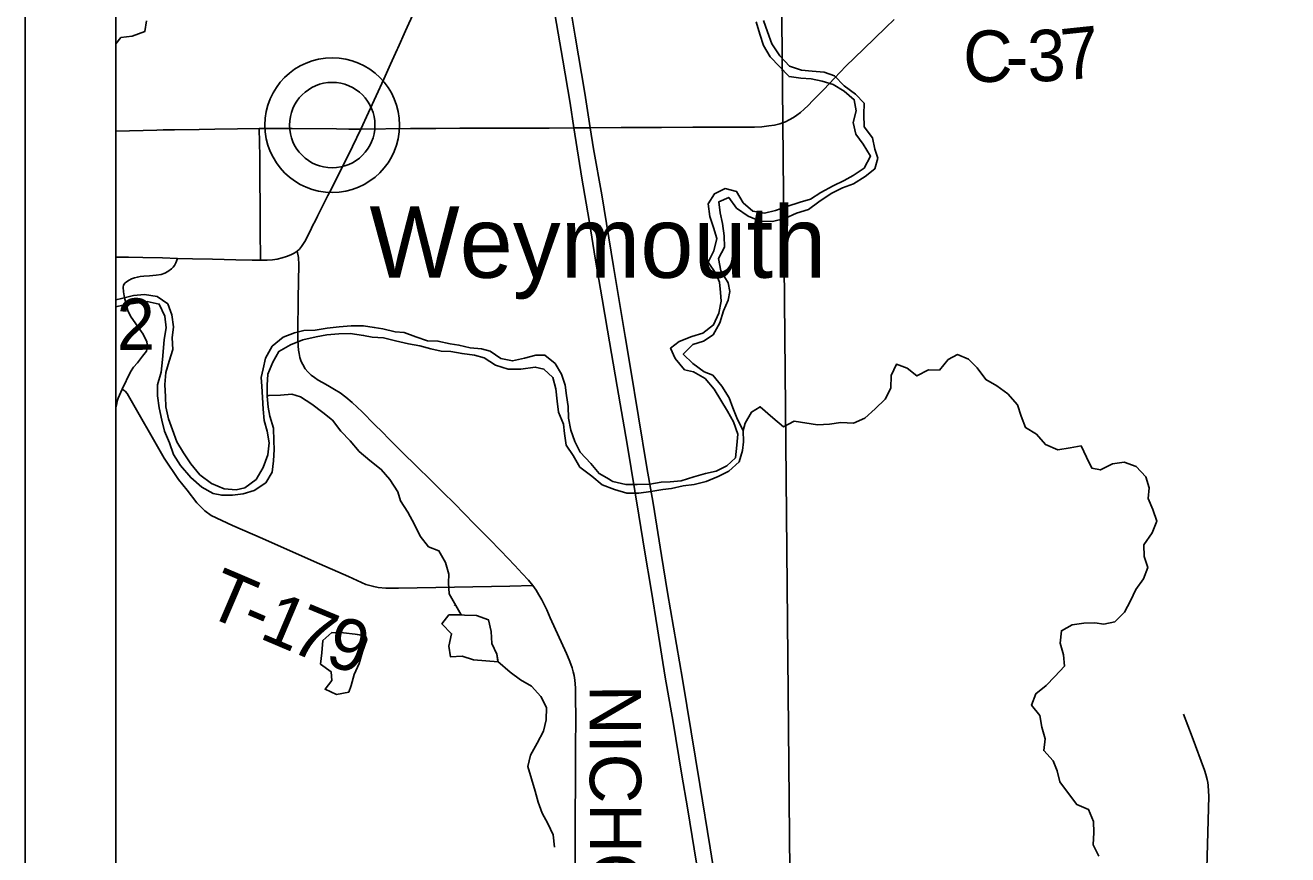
# Model space of a CAD drawing. Extents: x 0 to 34, y 0 to 22.
# Drawn here: x 2 to 3.395, y 17.117 to 18.033 of the extents above; entities that cross this region are included whole.
import ezdxf

# ---------------------------------------------------------------- set-up
doc = ezdxf.new("R2010")
doc.units = 0
for name, color, linetype in [('GM_X_Corporation', 7, 'Continuous'), ('GM_X_County_Road', 7, 'Continuous'), ('GM_X_County_Road_Text', 7, 'Continuous'), ('GM_X_Interstate_Route', 7, 'Continuous'), ('GM_X_Minor_Lake', 7, 'Continuous'), ('GM_X_Minor_River', 7, 'Continuous'), ('GM_X_Township_Road', 7, 'Continuous'), ('GM_X_Township_Road_Text', 7, 'Continuous'), ('GM_X_Unincorporated', 7, 'Continuous'), ('GM_X_Unincorporated_Location', 7, 'Continuous'), ('GM_X_Unincorporated_Text', 7, 'Continuous'), ('SH_Data', 7, 'Continuous')]:
    doc.layers.add(name, color=color, linetype=linetype)

msp = doc.modelspace()

# ---------------------------------------------------------------- linework, layer by layer
at = {"layer": 'GM_X_Corporation'}
for points in [[(2.1, 20.9), (2.1, 14.1), (7.9734, 14.1), (7.9726, 14.5453), (7.9765, 15.2637), (7.9792, 15.5481), (7.979, 15.5988), (7.9808, 15.7192), (7.9807, 15.9078), (7.9821, 16.2487), (7.9825, 16.3395), (7.9818, 16.3982), (7.9825, 16.6077), (7.9838, 16.7968), (7.9877, 17.3871), (7.9891, 17.5498), (7.991, 17.7727), (7.9901, 18.1613)], [(3.735, 14.5275), (3.3839, 14.5264), (3.3511, 14.525), (2.8655, 14.5214), (2.8502, 15.8768), (2.8488, 16.2), (2.8487, 16.2273), (2.8487, 16.232), (2.8477, 16.3135), (2.8476, 16.3157), (2.8477, 16.7834), (2.837, 17.9259), (2.8293, 18.7154)]]:
    msp.add_lwpolyline(points, dxfattribs=at)
msp.add_lwpolyline([(2.1, 19.0167), (2.1, 14.5179), (2.2213, 14.5194), (2.2958, 14.5199), (2.3573, 14.5203), (2.3767, 14.5206), (2.4262, 14.5205), (2.6122, 14.5212), (2.8483, 14.5213), (2.8655, 14.5214), (2.8502, 15.8768), (2.8488, 16.2), (2.8487, 16.2273), (2.8487, 16.232), (2.8477, 16.3135), (2.8476, 16.3157), (2.8477, 16.7834), (2.837, 17.9259), (2.8293, 18.7154), (2.8247, 19.0323), (2.4392, 19.024), (2.4288, 19.0238), (2.421, 19.0236)], close=True, dxfattribs=at)
at = {"layer": 'GM_X_County_Road'}
for points in [[(2.1, 17.7765), (2.1066, 17.7766), (2.114, 17.7766), (2.13, 17.7764), (2.1515, 17.7758), (2.168, 17.7753), (2.1846, 17.7749), (2.2067, 17.7744), (2.2326, 17.7736), (2.2505, 17.7732), (2.2598, 17.7732), (2.2673, 17.7735), (2.273, 17.7739), (2.2783, 17.7746), (2.2837, 17.7759), (2.2885, 17.7773), (2.2935, 17.7793), (2.297, 17.7809), (2.3005, 17.7833), (2.3028, 17.7855), (2.3052, 17.7884), (2.3088, 17.7938), (2.3139, 17.8039), (2.3186, 17.8133), (2.3195, 17.815), (2.3229, 17.8219), (2.324, 17.824), (2.3248, 17.8257), (2.3263, 17.8286), (2.3343, 17.8446), (2.3357, 17.8473), (2.3361, 17.848), (2.3504, 17.8765), (2.3616, 17.8989), (2.3708, 17.9182), (2.3961, 17.9731), (2.4036, 17.9898), (2.411, 18.0061), (2.4115, 18.0073), (2.4202, 18.0266), (2.4375, 18.0648)], [(2.8364, 17.925), (2.8398, 17.9263), (2.8439, 17.9283), (2.8485, 17.9309), (2.8523, 17.9334), (2.8565, 17.9366), (2.8604, 17.94), (2.8647, 17.9442), (2.87, 17.9496), (2.8758, 17.9557), (2.882, 17.962), (2.8939, 17.9744), (2.9065, 17.9875), (2.9258, 18.0062), (2.9505, 18.0302), (2.96, 18.0392)], [(2.3708, 17.9182), (2.4257, 17.9187), (2.4537, 17.9189), (2.48, 17.9191), (2.551, 17.9192), (2.5787, 17.9193), (2.606, 17.9194), (2.6241, 17.9195), (2.6583, 17.9197), (2.7027, 17.92), (2.7376, 17.9201), (2.7736, 17.9202), (2.796, 17.9201), (2.8055, 17.9203), (2.8136, 17.9207), (2.8215, 17.9216), (2.8275, 17.9225), (2.8335, 17.924), (2.8364, 17.925)], [(2.6075, 17.0962), (2.6076, 17.1188), (2.6076, 17.1408), (2.6076, 17.1683), (2.6078, 17.189), (2.6079, 17.2148), (2.608, 17.2395), (2.6081, 17.2631), (2.6079, 17.2952), (2.6079, 17.3006), (2.6075, 17.3053), (2.6072, 17.3094), (2.6064, 17.3145), (2.6054, 17.3189), (2.6041, 17.3232), (2.6028, 17.3272), (2.601, 17.3319), (2.598, 17.3389), (2.58, 17.3783), (2.576, 17.3872), (2.5706, 17.3984), (2.5675, 17.4038), (2.5644, 17.4089), (2.5608, 17.4142), (2.5559, 17.4199), (2.5489, 17.4275), (2.5409, 17.4363), (2.5255, 17.4523), (2.5123, 17.4657), (2.4955, 17.4827), (2.4857, 17.4928), (2.4734, 17.5052), (2.4622, 17.5163), (2.4477, 17.5306), (2.4327, 17.5454), (2.4165, 17.5614), (2.4017, 17.576), (2.3945, 17.5833), (2.3857, 17.592), (2.3721, 17.6057), (2.3613, 17.6161), (2.3612, 17.6161), (2.3541, 17.6221), (2.3477, 17.6268), (2.3416, 17.6306), (2.3343, 17.635), (2.3285, 17.6382), (2.3235, 17.641), (2.3194, 17.6437), (2.3158, 17.6464), (2.312, 17.6501), (2.3093, 17.6534), (2.3066, 17.6581), (2.3049, 17.6616), (2.3035, 17.666), (2.3024, 17.6701), (2.3018, 17.6741), (2.3013, 17.6789), (2.3012, 17.6857), (2.3011, 17.6937), (2.3014, 17.7306), (2.3018, 17.7501), (2.3023, 17.7681), (2.3017, 17.7762), (2.3005, 17.7833)]]:
    msp.add_lwpolyline(points, dxfattribs=at)
at = {"layer": 'GM_X_Interstate_Route'}
for points in [[(2.7659, 17.0664), (2.7566, 17.1244), (2.7451, 17.1942), (2.726, 17.3106), (2.7095, 17.4063), (2.7027, 17.4473), (2.6936, 17.505), (2.6866, 17.5444), (2.6681, 17.6564), (2.6627, 17.689), (2.6498, 17.7663), (2.6368, 17.8455), (2.6278, 17.8963), (2.6241, 17.9195), (2.6182, 17.9577), (2.6074, 18.0208), (2.5891, 18.1314)], [(2.7437, 17.0939), (2.732, 17.1664), (2.7249, 17.2068), (2.7158, 17.2631), (2.707, 17.3127), (2.6984, 17.3663), (2.6915, 17.4095), (2.6844, 17.4509), (2.6778, 17.4918), (2.6648, 17.5701), (2.6537, 17.634), (2.6432, 17.6961), (2.6374, 17.7307), (2.63, 17.7732), (2.6231, 17.8172), (2.615, 17.8638), (2.606, 17.9194), (2.6019, 17.9467), (2.5937, 17.9944), (2.5837, 18.054)]]:
    msp.add_lwpolyline(points, dxfattribs=at)
at = {"layer": 'GM_X_Minor_Lake'}
for points in [[(2.4739, 17.3922), (2.474, 17.392)], [(2.4822, 17.3817), (2.468, 17.3815), (2.4602, 17.3719), (2.471, 17.3607), (2.4678, 17.3469), (2.4699, 17.3352), (2.4828, 17.3362), (2.495, 17.3319), (2.5223, 17.3297)], [(2.4814, 17.3817), (2.468, 17.3815), (2.4602, 17.3719), (2.471, 17.3607), (2.4678, 17.3469), (2.4699, 17.3352), (2.4828, 17.3362), (2.495, 17.3319), (2.5223, 17.3297)], [(2.5222, 17.3301), (2.5209, 17.3383), (2.5154, 17.3501), (2.5148, 17.3633), (2.5116, 17.3762), (2.4986, 17.3809), (2.4854, 17.3814), (2.481, 17.3818)], [(2.5223, 17.3297), (2.5209, 17.3383), (2.5154, 17.3501), (2.5148, 17.3633), (2.5116, 17.3762), (2.4986, 17.3809), (2.4854, 17.3814), (2.4822, 17.3817)], [(2.3758, 17.3585), (2.3646, 17.3602), (2.3517, 17.3617), (2.3385, 17.3621), (2.3287, 17.3533), (2.3275, 17.3397), (2.326, 17.3272), (2.3378, 17.3188), (2.3385, 17.3093), (2.3313, 17.2995), (2.3438, 17.2938), (2.3574, 17.2961)], [(2.3767, 17.3583), (2.3646, 17.3602), (2.3517, 17.3617), (2.3385, 17.3621), (2.3287, 17.3533), (2.3275, 17.3397), (2.326, 17.3272), (2.3378, 17.3188), (2.3385, 17.3093), (2.3313, 17.2995), (2.3438, 17.2938), (2.3574, 17.2961)], [(2.3574, 17.2961), (2.3601, 17.3037), (2.3635, 17.3158), (2.3688, 17.328), (2.3726, 17.3409), (2.3775, 17.3545), (2.3758, 17.3585)], [(2.3574, 17.2961), (2.3601, 17.3037), (2.3635, 17.3158), (2.3688, 17.328), (2.3726, 17.3409), (2.3775, 17.3545), (2.3758, 17.3584)]]:
    msp.add_lwpolyline(points, dxfattribs=at)
at = {"layer": 'GM_X_Minor_River'}
for points in [[(2.1, 18.0122), (2.1057, 18.0193), (2.1182, 18.0207), (2.1321, 18.0259), (2.1341, 18.0377)], [(2.8075, 18.0366), (2.8115, 18.023), (2.8155, 18.0105), (2.8229, 17.9978), (2.8333, 17.9873), (2.8437, 17.9761), (2.8566, 17.9745), (2.868, 17.9735), (2.8805, 17.9711), (2.8923, 17.9675), (2.9045, 17.9601), (2.9157, 17.9505), (2.9178, 17.9384), (2.9146, 17.9254), (2.9175, 17.9126), (2.9256, 17.9013), (2.9338, 17.8882), (2.9268, 17.8748)], [(2.9386, 17.8742), (2.9418, 17.886), (2.9386, 17.8958), (2.9361, 17.9083), (2.9268, 17.9207), (2.9265, 17.9343), (2.9267, 17.9469), (2.9171, 17.9566), (2.9048, 17.9658), (2.894, 17.977), (2.8826, 17.981), (2.8693, 17.9819), (2.8576, 17.9832), (2.8443, 17.9875), (2.8335, 17.9991), (2.8249, 18.0122), (2.8198, 18.0254), (2.8154, 18.0382)], [(2.2409, 17.5152), (2.253, 17.5188), (2.2657, 17.5274), (2.2727, 17.5393), (2.2743, 17.5518), (2.2749, 17.5644), (2.2747, 17.5739), (2.2741, 17.5879), (2.2701, 17.6011), (2.2684, 17.6109), (2.2674, 17.6231), (2.2672, 17.6352), (2.2681, 17.6473), (2.2736, 17.6607), (2.2802, 17.6726), (2.2929, 17.68), (2.3068, 17.6852), (2.3215, 17.6885), (2.3332, 17.691), (2.3464, 17.692), (2.3589, 17.6922), (2.3737, 17.6902), (2.3831, 17.6884), (2.3956, 17.6875), (2.4089, 17.6843), (2.4234, 17.6808), (2.4359, 17.6787), (2.4481, 17.6755), (2.4595, 17.6727), (2.47, 17.6725), (2.4826, 17.6701), (2.4962, 17.6684), (2.5069, 17.6656), (2.5195, 17.6574), (2.5336, 17.6531), (2.5476, 17.653), (2.5634, 17.6552), (2.5729, 17.6531), (2.5829, 17.6438), (2.5861, 17.6313), (2.5875, 17.6177), (2.5892, 17.6056), (2.5944, 17.5924), (2.5957, 17.5818), (2.5975, 17.5689), (2.6052, 17.5577), (2.6126, 17.5449), (2.6257, 17.5349), (2.6372, 17.5252), (2.6509, 17.5201), (2.6646, 17.5162), (2.6778, 17.5161), (2.691, 17.5178), (2.7042, 17.5199), (2.714, 17.5212), (2.7269, 17.5241), (2.7389, 17.5255), (2.7521, 17.5291), (2.7653, 17.5343), (2.7773, 17.5402), (2.7888, 17.5506), (2.7924, 17.5632), (2.7933, 17.5727), (2.7931, 17.5852), (2.7869, 17.5973), (2.7817, 17.6101), (2.7777, 17.6214), (2.7696, 17.6341), (2.7595, 17.6465), (2.75, 17.6501), (2.7373, 17.6594), (2.7269, 17.6694), (2.7373, 17.6802), (2.7494, 17.6839), (2.7599, 17.6909), (2.7672, 17.7043), (2.7715, 17.7173), (2.7766, 17.7291), (2.7783, 17.7386), (2.7766, 17.7485), (2.7684, 17.7616), (2.7659, 17.7752), (2.7725, 17.7878), (2.7719, 17.8004), (2.7702, 17.814), (2.7677, 17.8257), (2.7663, 17.8378), (2.7772, 17.8426), (2.7858, 17.8309), (2.7984, 17.8221), (2.8117, 17.8166), (2.8254, 17.8161), (2.8389, 17.8194), (2.8521, 17.8253), (2.8652, 17.8293), (2.8768, 17.8379), (2.8903, 17.8468), (2.9026, 17.8531), (2.915, 17.8575), (2.9278, 17.8657), (2.9386, 17.8742)], [(2.9268, 17.8748), (2.9145, 17.867), (2.9048, 17.8615), (2.8924, 17.8556), (2.8789, 17.8481), (2.8673, 17.8407), (2.856, 17.8375), (2.8413, 17.8327), (2.8289, 17.8283), (2.8165, 17.8254), (2.8036, 17.8275), (2.7932, 17.8368), (2.7858, 17.8492), (2.7733, 17.8524), (2.7613, 17.8465), (2.7543, 17.8357), (2.7564, 17.8217), (2.7604, 17.8093), (2.764, 17.7972), (2.7605, 17.7835), (2.7543, 17.7712), (2.7628, 17.7588), (2.7668, 17.749), (2.7681, 17.7377), (2.7687, 17.7282), (2.7662, 17.7149), (2.7604, 17.7019), (2.7485, 17.6926), (2.7364, 17.689), (2.7225, 17.6834), (2.7128, 17.676), (2.718, 17.6647), (2.7284, 17.6524), (2.7383, 17.6499), (2.7509, 17.6425), (2.7609, 17.631), (2.7683, 17.6186), (2.7757, 17.6066), (2.7824, 17.5949), (2.7871, 17.5813), (2.7862, 17.5692), (2.7846, 17.5551), (2.7749, 17.5462), (2.7633, 17.5403), (2.7516, 17.5378), (2.7384, 17.5342), (2.7245, 17.5298), (2.7124, 17.5284), (2.7026, 17.5283), (2.6898, 17.5258), (2.6761, 17.5255), (2.6633, 17.5257), (2.6489, 17.5288), (2.6464, 17.5304), (2.645, 17.5314), (2.6339, 17.5377), (2.6247, 17.5489), (2.6131, 17.5612), (2.6072, 17.5732), (2.6025, 17.5857), (2.6, 17.5989), (2.5997, 17.6118), (2.598, 17.6239), (2.5963, 17.6353), (2.5923, 17.6473), (2.5853, 17.6594), (2.5738, 17.6683), (2.5639, 17.6685), (2.5515, 17.6652), (2.5383, 17.662), (2.5254, 17.6648), (2.5135, 17.6729), (2.504, 17.6754), (2.4915, 17.6767), (2.479, 17.6795), (2.4695, 17.6809), (2.4558, 17.684), (2.4445, 17.6842), (2.4316, 17.6885), (2.4186, 17.6936), (2.4088, 17.6942), (2.3951, 17.6974), (2.3856, 17.6991), (2.3735, 17.7008), (2.3602, 17.7009), (2.3466, 17.6999), (2.3334, 17.6982), (2.3202, 17.6961), (2.3077, 17.6955), (2.2976, 17.693), (2.2848, 17.6882), (2.2729, 17.6782), (2.2655, 17.6651), (2.2627, 17.6533), (2.2606, 17.6438), (2.2612, 17.6343), (2.2621, 17.6218), (2.2627, 17.6089), (2.2641, 17.5961), (2.2673, 17.5844), (2.2695, 17.5715)], [(2.2695, 17.5715), (2.2678, 17.5582), (2.2627, 17.5444), (2.255, 17.531), (2.2427, 17.5221), (2.2329, 17.5196), (2.2197, 17.5209), (2.2056, 17.5267), (2.1929, 17.5364), (2.1829, 17.5483), (2.1747, 17.5607), (2.1673, 17.5727), (2.1625, 17.5859), (2.1582, 17.598), (2.1553, 17.6112), (2.1551, 17.6226), (2.1541, 17.6362), (2.1554, 17.6492), (2.1589, 17.6617), (2.1629, 17.6747), (2.1622, 17.6876), (2.1639, 17.6998), (2.1618, 17.713), (2.1574, 17.7251), (2.1456, 17.7332), (2.1319, 17.7353), (2.1194, 17.7343), (2.1063, 17.731), (2.1, 17.7296)], [(2.1, 17.7218), (2.1079, 17.7238), (2.1219, 17.726), (2.1347, 17.7277), (2.148, 17.7249), (2.1543, 17.7114), (2.1556, 17.6985), (2.1536, 17.6859), (2.1526, 17.6764), (2.1517, 17.6635), (2.1501, 17.6498), (2.1461, 17.6357), (2.146, 17.6236), (2.1481, 17.6103), (2.151, 17.5967), (2.1539, 17.5846), (2.1594, 17.5715), (2.1638, 17.5586), (2.1715, 17.5466), (2.1828, 17.5332), (2.195, 17.5228), (2.2076, 17.5158), (2.2171, 17.5137), (2.2289, 17.5139), (2.2409, 17.5152)], [(2.7931, 17.5852), (2.7952, 17.5932), (2.8022, 17.6055), (2.8119, 17.6114), (2.8258, 17.5991), (2.8377, 17.5894), (2.8493, 17.5957), (2.8751, 17.5916), (2.8883, 17.5922), (2.9011, 17.594), (2.9148, 17.5934), (2.9275, 17.599), (2.9387, 17.609), (2.9499, 17.6199), (2.9561, 17.6321), (2.9566, 17.6458), (2.9624, 17.6584), (2.9742, 17.654), (2.985, 17.6455), (2.9977, 17.6522), (3.0098, 17.652), (3.0195, 17.6636), (3.0299, 17.6691), (3.0421, 17.664), (3.0514, 17.6543), (3.0611, 17.6415), (3.0733, 17.6345), (3.0856, 17.6256), (3.096, 17.6137), (3.1, 17.6012), (3.1048, 17.5884), (3.117, 17.5811), (3.127, 17.5698), (3.1407, 17.564), (3.1543, 17.5661), (3.1664, 17.5683), (3.1723, 17.5558), (3.1782, 17.5438), (3.1877, 17.5417), (3.2012, 17.5484), (3.214, 17.5501), (3.2273, 17.5454), (3.2377, 17.5342), (3.2417, 17.5218), (3.2404, 17.51), (3.2455, 17.4979), (3.2499, 17.4851), (3.2449, 17.4721), (3.2356, 17.4591), (3.2359, 17.4462), (3.2402, 17.4341), (3.2352, 17.4215), (3.2267, 17.4096), (3.2208, 17.3973), (3.2143, 17.3847), (3.2035, 17.3739), (3.1914, 17.3714), (3.1816, 17.3728), (3.1695, 17.3725), (3.1566, 17.3708), (3.1446, 17.3641), (3.1434, 17.3505), (3.147, 17.3376), (3.148, 17.3251), (3.1372, 17.3135), (3.1276, 17.3035), (3.1164, 17.2946), (3.1117, 17.282), (3.1209, 17.2704), (3.1231, 17.2575), (3.1267, 17.2447), (3.125, 17.2318), (3.1354, 17.2206), (3.1398, 17.2093), (3.143, 17.1972), (3.1523, 17.1844), (3.1616, 17.1721), (3.1746, 17.1666), (3.1801, 17.1534), (3.1803, 17.1413), (3.1798, 17.1276), (3.1861, 17.1152)], [(2.2674, 17.6231), (2.2689, 17.6238), (2.2818, 17.6241), (2.2946, 17.6254), (2.3041, 17.6226), (2.3167, 17.6144), (2.3286, 17.6052), (2.3394, 17.5966), (2.3487, 17.5846), (2.3591, 17.5738), (2.3687, 17.5622), (2.3806, 17.5522), (2.3933, 17.5422), (2.4029, 17.531), (2.4115, 17.5175), (2.4147, 17.5076), (2.4225, 17.4949), (2.4299, 17.4814), (2.4362, 17.4686), (2.4455, 17.4566), (2.4569, 17.4522), (2.4643, 17.4395), (2.468, 17.4266), (2.4677, 17.4171), (2.4683, 17.405), (2.4814, 17.3818)], [(2.5222, 17.3301), (2.5357, 17.3182), (2.5472, 17.31), (2.5594, 17.303), (2.5694, 17.2914), (2.5757, 17.2794), (2.5756, 17.2657), (2.5724, 17.2532), (2.5654, 17.2398), (2.5581, 17.2267), (2.5553, 17.2142), (2.5633, 17.187), (2.5666, 17.1749), (2.5709, 17.1628), (2.5772, 17.1512), (2.5831, 17.1388), (2.5845, 17.1251)]]:
    msp.add_lwpolyline(points, dxfattribs=at)
at = {"layer": 'GM_X_Township_Road'}
for points in [[(2.1, 17.9159), (2.1455, 17.9171), (2.1525, 17.9172), (2.165, 17.9174), (2.1923, 17.9178), (2.2095, 17.9181), (2.2345, 17.9185), (2.2583, 17.9187), (2.2948, 17.9189), (2.3439, 17.9183), (2.3574, 17.9182), (2.3708, 17.9182)], [(2.2598, 17.7732), (2.2596, 17.8073), (2.259, 17.8878), (2.2583, 17.9187)], [(2.1, 17.6104), (2.101, 17.6147), (2.1017, 17.6175), (2.1026, 17.6208), (2.1071, 17.631), (2.1162, 17.6501), (2.1197, 17.6552), (2.124, 17.6601), (2.1297, 17.6674), (2.1338, 17.673), (2.135, 17.6777), (2.1344, 17.683), (2.1301, 17.6915), (2.1249, 17.6993), (2.1163, 17.7114), (2.1135, 17.7176), (2.1095, 17.7319), (2.1084, 17.7382), (2.1082, 17.7434), (2.1087, 17.7457), (2.1101, 17.7478), (2.1119, 17.7495), (2.1148, 17.7513), (2.1175, 17.7527), (2.1206, 17.7537), (2.1239, 17.7546), (2.1269, 17.7553), (2.131, 17.7558), (2.1373, 17.7562), (2.1446, 17.7569), (2.1503, 17.7576), (2.1541, 17.7589), (2.1576, 17.7607), (2.1617, 17.7636), (2.1635, 17.7655), (2.165, 17.7676), (2.1664, 17.7703), (2.168, 17.7753)], [(2.1071, 17.631), (2.1103, 17.6287), (2.1124, 17.6261), (2.1535, 17.5546), (2.1694, 17.5313), (2.1789, 17.5192), (2.1896, 17.5053), (2.1931, 17.5017), (2.1983, 17.4967), (2.2054, 17.4913), (2.2289, 17.4804), (2.2621, 17.4661), (2.3191, 17.4406), (2.3569, 17.424), (2.3764, 17.4153), (2.3849, 17.4128), (2.39, 17.4119), (2.3985, 17.4112), (2.4122, 17.4113), (2.4741, 17.4123), (2.5352, 17.4132), (2.5608, 17.4142)], [(3.253, 16.9727), (3.2912, 17.0303), (3.2965, 17.0387), (3.2992, 17.0446), (3.3012, 17.05), (3.3022, 17.0536), (3.3029, 17.0585), (3.3036, 17.0628), (3.3041, 17.0686), (3.3044, 17.0752), (3.3074, 17.1813), (3.3072, 17.1868), (3.3067, 17.1931), (3.3063, 17.1965), (3.3057, 17.1998), (3.3042, 17.2054), (3.3027, 17.2102), (3.2892, 17.247), (3.2793, 17.2719)]]:
    msp.add_lwpolyline(points, dxfattribs=at)
at = {"layer": 'GM_X_Unincorporated'}
for radius in [0.0744, 0.0472]:
    msp.add_circle((2.3391, 17.9225), radius, dxfattribs=at)
at = {"layer": 'GM_X_Unincorporated_Location'}
msp.add_line((2.3391, 17.9225), (2.3391, 17.9225), dxfattribs=at)
at = {"layer": 'SH_Data'}
for p, q in [((2, 21), (2, 14)), ((2.1, 20.9), (2.1, 14.1))]:
    msp.add_line(p, q, dxfattribs=at)

# ---------------------------------------------------------------- texts
at = {"layer": 'GM_X_County_Road_Text'}
for s, height, rotation, p in [('C', 0.0568, 0.039, (3.036, 17.9702)), ('3', 0.0568, 1.6963, (3.1078, 17.9704)), ('7', 0.0568, 5.9791, (3.1474, 17.9717)), ('-', 0.0568, 0.3996, (3.0831, 17.9702)), ('2', 0.0568, 0.4527, (2.1012, 17.6741)), ('NICHOLS', 0.05682, 270.1573, (2.6233, 17.3043))]:
    msp.add_text(s, height=height, rotation=rotation, dxfattribs=at).set_placement(p)
at = {"layer": 'GM_X_Township_Road_Text'}
for s, rotation, p in [('T', 336.8504, (2.1964, 17.3824)), ('1', 337.0043, (2.2571, 17.3565)), ('7', 337.5113, (2.2898, 17.3426)), ('-', 336.877, (2.2355, 17.3657)), ('9', 344.7222, (2.3295, 17.3267))]:
    msp.add_text(s, height=0.0568, rotation=rotation, dxfattribs=at).set_placement(p)
at = {"layer": 'GM_X_Unincorporated_Text'}
msp.add_text('Weymouth', height=0.07898, rotation=0, dxfattribs=at).set_placement((2.3802, 17.7539))

doc.saveas('drawing.dxf')
